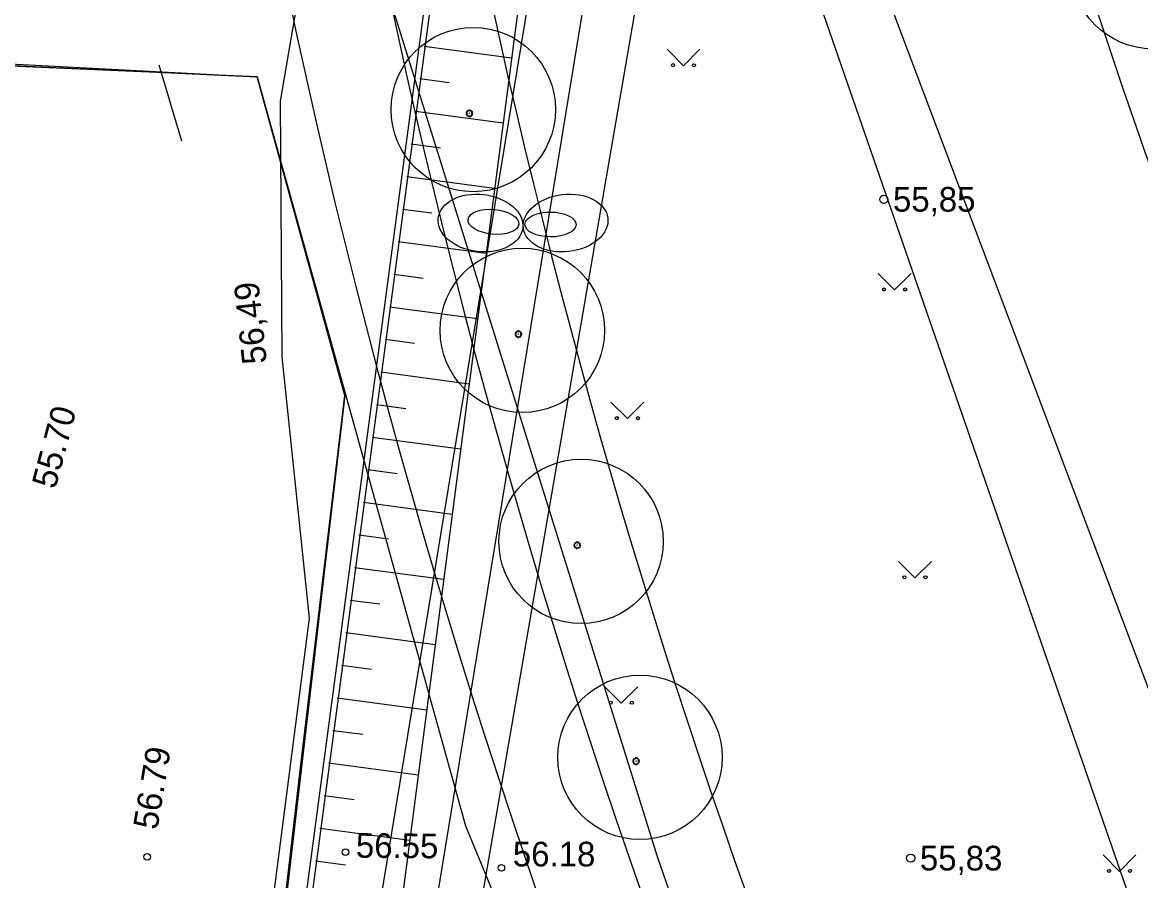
# Model space of a CAD drawing. Extents: x 9156 to 9809, y 2728 to 4000.
# Drawn here: x 9410.12 to 9444.15, y 3846.32 to 3872.43 of the extents above; entities that cross this region are included whole.
import ezdxf

# ---------------------------------------------------------------- set-up
doc = ezdxf.new("R2010")
doc.units = 0
for name, color, linetype in [('Level 12', 7, 'Continuous'), ('Level 14', 7, 'Continuous'), ('Level 16', 7, 'Continuous'), ('Level 17', 7, 'Continuous'), ('Level 18', 7, 'Continuous'), ('Level 41', 7, 'Continuous'), ('Level 54', 7, 'Continuous'), ('Level 56', 7, 'Continuous'), ('Level 6', 7, 'Continuous'), ('Level 7', 7, 'Continuous'), ('Level 8', 7, 'Continuous'), ('Level 9', 7, 'Continuous')]:
    doc.layers.add(name, color=color, linetype=linetype)

# ---------------------------------------------------------------- blocks, each defined once
blk = doc.blocks.new('MURU')
at = {"layer": 'Level 41'}
for p, q in [((-0.5, 0.5), (0, 0)), ((0, 0), (0.5, 0.5))]:
    blk.add_line(p, q, dxfattribs=at)
for centre in [(-0.32, 0.015), (0.32, 0.014)]:
    blk.add_circle(centre, 0.0466, dxfattribs=at)

msp = doc.modelspace()

# ---------------------------------------------------------------- linework, layer by layer
at = {"layer": 'Level 12'}
for p, q in [((9429.455, 3847.022), (9420.545, 3875.576)), ((9414.972, 3868.817), (9414.279, 3871.127)), ((9432.928, 3837.052), (9429.455, 3847.022))]:
    msp.add_line(p, q, dxfattribs=at)
at = {"layer": 'Level 14'}
msp.add_line((9444.967, 3842.49), (9431.28, 3881.958), dxfattribs=at)
at = {"layer": 'Level 16'}
msp.add_line((9449.679, 3838.123), (9432.161, 3884.564), dxfattribs=at)
at = {"layer": 'Level 17'}
for centre, radius, start, end in [((9631.829, 3934.713), 192.9, 187.13653, 212.29226), ((9631.829, 3934.713), 195.9, 187.89598, 211.0202), ((9639.344, 3919.894), 226, 185.96508, 207.05054), ((9639.344, 3919.894), 223, 186.63117, 207.05059)]:
    msp.add_arc(centre, radius, start, end, dxfattribs=at)
at = {"layer": 'Level 18'}
for centre, radius, start, end in [((9631.829, 3934.713), 198.9, 190.27283, 207.99609), ((9639.344, 3919.894), 220, 188.1609, 207.05049)]:
    msp.add_arc(centre, radius, start, end, dxfattribs=at)
at = {"layer": 'Level 54'}
for p, q in [((9428.052, 3915.601), (9415.976, 3825.147)), ((9427.378, 3909.376), (9416.171, 3825.133)), ((9419.432, 3836.064), (9425.772, 3874.586)), ((9429.001, 3874.205), (9422.209, 3834.878)), ((9422.347, 3871.71), (9425.006, 3871.355)), ((9422.215, 3870.719), (9423.102, 3870.601)), ((9422.082, 3869.728), (9424.747, 3869.372)), ((9421.95, 3868.737), (9422.839, 3868.618)), ((9421.818, 3867.746), (9424.489, 3867.389)), ((9421.685, 3866.754), (9422.577, 3866.635)), ((9421.553, 3865.763), (9424.23, 3865.406)), ((9421.42, 3864.772), (9422.314, 3864.653)), ((9421.288, 3863.781), (9423.972, 3863.422)), ((9421.156, 3862.79), (9422.051, 3862.67)), ((9421.023, 3861.798), (9423.713, 3861.439)), ((9420.891, 3860.807), (9421.789, 3860.687)), ((9420.758, 3859.816), (9423.455, 3859.456)), ((9420.626, 3858.825), (9421.526, 3858.705)), ((9420.494, 3857.834), (9423.196, 3857.473)), ((9420.361, 3856.842), (9421.263, 3856.722)), ((9420.229, 3855.851), (9422.938, 3855.489)), ((9420.097, 3854.86), (9421, 3854.739)), ((9419.964, 3853.869), (9422.679, 3853.506)), ((9419.832, 3852.878), (9420.738, 3852.757)), ((9419.699, 3851.886), (9422.421, 3851.523)), ((9419.567, 3850.895), (9420.475, 3850.774)), ((9419.435, 3849.904), (9422.162, 3849.54)), ((9419.302, 3848.913), (9420.212, 3848.791)), ((9419.17, 3847.922), (9421.904, 3847.556)), ((9419.037, 3846.93), (9419.95, 3846.809))]:
    msp.add_line(p, q, dxfattribs=at)
for points in [[(9415.997, 3832.136), (9418.853, 3854.304), (9418.853, 3854.304), (9418.027, 3862.261), (9417.976, 3870.031), (9426.142, 3917.687)], [(9419.311, 3824.906), (9430.024, 3890.161), (9433.2, 3889.656), (9434.423, 3896.884), (9431.507, 3897.561), (9431.927, 3902.125)], [(9428.218, 3901.358), (9428.633, 3899.185), (9420.75, 3838.705)]]:
    msp.add_lwpolyline(points, dxfattribs=at)
for centre, radius in [((9436.332, 3867.048), 0.125), ((9419.952, 3847.192), 0.1), ((9413.916, 3847.05), 0.1), ((9437.151, 3847.008), 0.125), ((9437.151, 3847.008), 0.125), ((9424.694, 3846.712), 0.1)]:
    msp.add_circle(centre, radius, dxfattribs=at)
at = {"layer": 'Level 56'}
for centre, radius, start, end in [((9631.829, 3934.713), 192.9, 187.13653, 212.29226), ((9631.829, 3934.713), 195.9, 187.89598, 211.0202), ((9631.829, 3934.713), 198.9, 190.27283, 207.99609), ((9639.344, 3919.894), 226, 185.96508, 207.05054), ((9639.344, 3919.894), 223, 186.63117, 207.05059), ((9639.344, 3919.894), 220, 188.1609, 207.05049)]:
    msp.add_arc(centre, radius, start, end, dxfattribs=at)
at = {"layer": 'Level 6'}
msp.add_line((9418.608, 3850.018), (9419.931, 3861.081), dxfattribs=at)
msp.add_lwpolyline([(9406.335, 3871.284), (9417.264, 3870.77), (9419.931, 3861.081), (9410.086, 3776.653), (9389.428, 3778.75), (9392.066, 3801.386), (9401.769, 3871.605)], close=True, dxfattribs=at)
for points in [[(9419.931, 3861.081), (9417.264, 3870.77), (9406.215, 3871.248), (9405.858, 3871.32)], [(9397.586, 3777.922), (9410.086, 3776.653), (9418.608, 3850.018)]]:
    msp.add_lwpolyline(points, dxfattribs=at)
at = {"layer": 'Level 7'}
for p, q in [((9397.252, 3871.834), (9417.264, 3870.77)), ((9417.264, 3870.77), (9423.602, 3847.995)), ((9423.602, 3847.995), (9436.729, 3816.345))]:
    msp.add_line(p, q, dxfattribs=at)
at = {"layer": 'Level 8'}
for centre, major_axis, ratio in [((9424.058, 3866.327), (1.285, -0.15), 0.674652), ((9424.058, 3866.327), (1.285, -0.15), 0.674652), ((9424.058, 3866.327), (1.285, -0.15), 0.674652), ((9424.058, 3866.327), (1.285, -0.15), 0.674652), ((9426.65, 3866.327), (-1.285, -0.15), 0.674652), ((9426.65, 3866.327), (-1.285, -0.15), 0.674652), ((9426.65, 3866.327), (-1.285, -0.15), 0.674652), ((9426.65, 3866.327), (-1.285, -0.15), 0.674652), ((9424.453, 3866.364), (0.774, -0.072), 0.486914), ((9424.453, 3866.364), (0.774, -0.072), 0.486914), ((9424.453, 3866.364), (0.774, -0.072), 0.486914), ((9424.453, 3866.364), (0.774, -0.072), 0.486914), ((9426.19, 3866.284), (-0.778, 0.002), 0.486914), ((9426.19, 3866.284), (-0.778, 0.002), 0.486914), ((9426.19, 3866.284), (-0.778, 0.002), 0.486914), ((9426.19, 3866.284), (-0.778, 0.002), 0.486914)]:
    msp.add_ellipse(centre, major_axis=major_axis, ratio=ratio, dxfattribs=at)
at = {"layer": 'Level 9'}
for p, q in [((9423.662, 3869.715), (9423.645, 3869.729)), ((9423.667, 3869.748), (9423.678, 3869.729)), ((9423.7, 3869.739), (9423.693, 3869.76)), ((9423.721, 3869.764), (9423.721, 3869.742)), ((9423.743, 3869.739), (9423.749, 3869.76)), ((9423.775, 3869.748), (9423.765, 3869.729)), ((9423.781, 3869.715), (9423.797, 3869.729)), ((9423.643, 3869.675), (9423.622, 3869.678)), ((9423.622, 3869.649), (9423.643, 3869.653)), ((9423.63, 3869.705), (9423.65, 3869.697)), ((9423.65, 3869.63), (9423.63, 3869.621)), ((9423.645, 3869.597), (9423.661, 3869.612)), ((9423.679, 3869.597), (9423.667, 3869.579)), ((9423.692, 3869.567), (9423.698, 3869.588)), ((9423.732, 3869.662), (9423.711, 3869.662)), ((9423.721, 3869.651), (9423.721, 3869.672)), ((9423.721, 3869.584), (9423.721, 3869.562)), ((9423.749, 3869.566), (9423.744, 3869.587)), ((9423.763, 3869.596), (9423.776, 3869.578)), ((9423.798, 3869.598), (9423.782, 3869.612)), ((9423.813, 3869.705), (9423.793, 3869.695)), ((9423.793, 3869.631), (9423.813, 3869.622)), ((9423.799, 3869.674), (9423.821, 3869.678)), ((9423.821, 3869.649), (9423.8, 3869.653)), ((9425.113, 3862.931), (9425.135, 3862.934)), ((9425.135, 3862.957), (9425.114, 3862.959)), ((9425.122, 3862.987), (9425.142, 3862.979)), ((9425.154, 3862.997), (9425.137, 3863.011)), ((9425.159, 3863.03), (9425.17, 3863.011)), ((9425.191, 3863.021), (9425.185, 3863.042)), ((9425.224, 3862.944), (9425.203, 3862.944)), ((9425.213, 3863.046), (9425.213, 3863.024)), ((9425.213, 3862.933), (9425.213, 3862.954)), ((9425.234, 3863.021), (9425.241, 3863.042)), ((9425.267, 3863.03), (9425.256, 3863.011)), ((9425.272, 3862.997), (9425.289, 3863.011)), ((9425.305, 3862.987), (9425.285, 3862.977)), ((9425.291, 3862.956), (9425.313, 3862.96)), ((9425.313, 3862.931), (9425.291, 3862.935)), ((9425.141, 3862.912), (9425.122, 3862.903)), ((9425.137, 3862.879), (9425.153, 3862.894)), ((9425.171, 3862.879), (9425.158, 3862.86)), ((9425.184, 3862.849), (9425.19, 3862.87)), ((9425.213, 3862.866), (9425.212, 3862.844)), ((9425.241, 3862.848), (9425.235, 3862.869)), ((9425.255, 3862.878), (9425.267, 3862.86)), ((9425.29, 3862.88), (9425.274, 3862.894)), ((9425.285, 3862.913), (9425.305, 3862.904)), ((9426.925, 3856.537), (9426.904, 3856.54)), ((9426.904, 3856.512), (9426.925, 3856.515)), ((9426.912, 3856.568), (9426.932, 3856.559)), ((9426.931, 3856.493), (9426.912, 3856.483)), ((9426.944, 3856.578), (9426.927, 3856.591)), ((9426.927, 3856.46), (9426.943, 3856.474)), ((9426.949, 3856.61), (9426.96, 3856.592)), ((9426.961, 3856.459), (9426.949, 3856.441)), ((9426.982, 3856.601), (9426.975, 3856.622)), ((9427.014, 3856.524), (9426.993, 3856.524)), ((9427.003, 3856.626), (9427.003, 3856.604)), ((9427.003, 3856.514), (9427.003, 3856.535)), ((9427.025, 3856.601), (9427.031, 3856.622)), ((9427.045, 3856.459), (9427.057, 3856.441)), ((9427.057, 3856.61), (9427.046, 3856.591)), ((9427.063, 3856.577), (9427.079, 3856.592)), ((9427.08, 3856.461), (9427.064, 3856.475)), ((9427.095, 3856.567), (9427.075, 3856.558)), ((9427.075, 3856.494), (9427.095, 3856.485)), ((9427.081, 3856.537), (9427.103, 3856.541)), ((9427.103, 3856.512), (9427.081, 3856.516)), ((9426.974, 3856.429), (9426.98, 3856.45)), ((9427.003, 3856.447), (9427.002, 3856.425)), ((9427.031, 3856.429), (9427.025, 3856.45)), ((9428.702, 3849.999), (9428.722, 3849.991)), ((9428.734, 3850.009), (9428.717, 3850.023)), ((9428.739, 3850.041), (9428.75, 3850.023)), ((9428.772, 3850.033), (9428.765, 3850.053)), ((9428.793, 3850.057), (9428.793, 3850.036)), ((9428.815, 3850.033), (9428.821, 3850.054)), ((9428.847, 3850.042), (9428.837, 3850.023)), ((9428.853, 3850.009), (9428.869, 3850.023)), ((9428.885, 3849.999), (9428.865, 3849.989)), ((9428.715, 3849.968), (9428.694, 3849.971)), ((9428.694, 3849.943), (9428.715, 3849.946)), ((9428.722, 3849.924), (9428.702, 3849.914)), ((9428.717, 3849.891), (9428.733, 3849.906)), ((9428.751, 3849.89), (9428.739, 3849.872)), ((9428.764, 3849.86), (9428.77, 3849.881)), ((9428.804, 3849.956), (9428.783, 3849.956)), ((9428.793, 3849.945), (9428.793, 3849.966)), ((9428.793, 3849.878), (9428.793, 3849.856)), ((9428.821, 3849.86), (9428.816, 3849.881)), ((9428.835, 3849.89), (9428.847, 3849.872)), ((9428.87, 3849.892), (9428.854, 3849.906)), ((9428.865, 3849.925), (9428.885, 3849.916)), ((9428.871, 3849.968), (9428.893, 3849.972)), ((9428.893, 3849.943), (9428.872, 3849.947))]:
    msp.add_line(p, q, dxfattribs=at)
for centre in [(9444.521, 3874.125), (9423.839, 3869.779), (9425.331, 3863.061), (9427.121, 3856.642), (9428.911, 3850.073)]:
    msp.add_circle(centre, 2.5, dxfattribs=at)
for centre, radius, start, end in [((9423.721, 3869.663), 0.101, 122.8434, 139.0222), ((9423.721, 3869.663), 0.0788, 105.9559, 123.0564), ((9423.721, 3869.663), 0.101, 90.0356, 106.342), ((9423.721, 3869.663), 0.0788, 74.31, 90.043), ((9423.721, 3869.663), 0.101, 57.6108, 74.1981), ((9423.721, 3869.663), 0.0788, 41.2062, 56.7795), ((9423.721, 3869.663), 0.101, 24.5394, 40.9852), ((9423.721, 3869.663), 0.101, 155.3123, 171.7042), ((9423.721, 3869.663), 0.101, 187.9671, 204.8625), ((9423.721, 3869.663), 0.0788, 171.5431, 187.6203), ((9423.721, 3869.663), 0.101, 220.7122, 237.1166), ((9423.721, 3869.663), 0.0788, 138.6432, 154.5795), ((9423.721, 3869.663), 0.0788, 204.4529, 220.4774), ((9423.721, 3869.663), 0.0788, 237.451, 253.0843), ((9423.721, 3869.663), 0.101, 253.2952, 269.5718), ((9423.721, 3869.663), 0.0788, 269.9461, 286.3473), ((9423.721, 3869.663), 0.101, 285.972, 302.5562), ((9423.721, 3869.663), 0.0788, 302.254, 320.086), ((9423.721, 3869.663), 0.0788, 8.0619, 24.0332), ((9423.721, 3869.663), 0.0788, 336.0557, 352.7558), ((9423.721, 3869.663), 0.101, 319.7777, 336.0738), ((9423.721, 3869.663), 0.101, 352.27, 8.583), ((9425.213, 3862.945), 0.101, 155.3123, 171.7042), ((9425.213, 3862.945), 0.101, 187.9671, 204.8625), ((9425.213, 3862.945), 0.0788, 171.5431, 187.6203), ((9425.213, 3862.945), 0.101, 122.8434, 139.0222), ((9425.213, 3862.945), 0.0788, 138.6432, 154.5795), ((9425.213, 3862.945), 0.0788, 105.9559, 123.0564), ((9425.213, 3862.945), 0.101, 90.0356, 106.342), ((9425.213, 3862.945), 0.0788, 74.31, 90.043), ((9425.213, 3862.945), 0.101, 57.6108, 74.1981), ((9425.213, 3862.945), 0.0788, 41.2062, 56.7795), ((9425.213, 3862.945), 0.0788, 8.0619, 24.0332), ((9425.213, 3862.945), 0.0788, 336.0557, 352.7558), ((9425.213, 3862.945), 0.101, 24.5394, 40.9852), ((9425.213, 3862.945), 0.101, 352.27, 8.583), ((9425.213, 3862.945), 0.101, 220.7122, 237.1166), ((9425.213, 3862.945), 0.0788, 204.4529, 220.4774), ((9425.213, 3862.945), 0.0788, 237.451, 253.0843), ((9425.213, 3862.945), 0.101, 253.2952, 269.5718), ((9425.213, 3862.945), 0.0788, 269.9461, 286.3473), ((9425.213, 3862.945), 0.101, 285.972, 302.5562), ((9425.213, 3862.945), 0.0788, 302.254, 320.086), ((9425.213, 3862.945), 0.101, 319.7777, 336.0738), ((9427.003, 3856.525), 0.101, 155.3123, 171.7042), ((9427.003, 3856.525), 0.101, 187.9671, 204.8625), ((9427.003, 3856.525), 0.0788, 171.5431, 187.6203), ((9427.003, 3856.525), 0.101, 122.8434, 139.0222), ((9427.003, 3856.525), 0.101, 220.7122, 237.1166), ((9427.003, 3856.525), 0.0788, 204.4529, 220.4774), ((9427.003, 3856.525), 0.0788, 138.6432, 154.5795), ((9427.003, 3856.525), 0.0788, 105.9559, 123.0564), ((9427.003, 3856.525), 0.0788, 237.451, 253.0843), ((9427.003, 3856.525), 0.101, 90.0356, 106.342), ((9427.003, 3856.525), 0.0788, 74.31, 90.043), ((9427.003, 3856.525), 0.101, 57.6108, 74.1981), ((9427.003, 3856.525), 0.0788, 302.254, 320.086), ((9427.003, 3856.525), 0.0788, 41.2062, 56.7795), ((9427.003, 3856.525), 0.0788, 8.0619, 24.0332), ((9427.003, 3856.525), 0.0788, 336.0557, 352.7558), ((9427.003, 3856.525), 0.101, 24.5394, 40.9852), ((9427.003, 3856.525), 0.101, 319.7777, 336.0738), ((9427.003, 3856.525), 0.101, 352.27, 8.583), ((9427.003, 3856.525), 0.101, 253.2952, 269.5718), ((9427.003, 3856.525), 0.0788, 269.9461, 286.3473), ((9427.003, 3856.525), 0.101, 285.972, 302.5562), ((9428.793, 3849.957), 0.101, 155.3123, 171.7042), ((9428.793, 3849.957), 0.101, 122.8434, 139.0222), ((9428.793, 3849.957), 0.0788, 138.6432, 154.5795), ((9428.793, 3849.957), 0.0788, 105.9559, 123.0564), ((9428.793, 3849.957), 0.101, 90.0356, 106.342), ((9428.793, 3849.957), 0.0788, 74.31, 90.043), ((9428.793, 3849.957), 0.101, 57.6108, 74.1981), ((9428.793, 3849.957), 0.0788, 41.2062, 56.7795), ((9428.793, 3849.957), 0.101, 24.5394, 40.9852), ((9428.793, 3849.957), 0.101, 187.9671, 204.8625), ((9428.793, 3849.957), 0.0788, 171.5431, 187.6203), ((9428.793, 3849.957), 0.101, 220.7122, 237.1166), ((9428.793, 3849.957), 0.0788, 204.4529, 220.4774), ((9428.793, 3849.957), 0.0788, 237.451, 253.0843), ((9428.793, 3849.957), 0.101, 253.2952, 269.5718), ((9428.793, 3849.957), 0.0788, 269.9461, 286.3473), ((9428.793, 3849.957), 0.101, 285.972, 302.5562), ((9428.793, 3849.957), 0.0788, 302.254, 320.086), ((9428.793, 3849.957), 0.0788, 8.0619, 24.0332), ((9428.793, 3849.957), 0.0788, 336.0557, 352.7558), ((9428.793, 3849.957), 0.101, 319.7777, 336.0738), ((9428.793, 3849.957), 0.101, 352.27, 8.583)]:
    msp.add_arc(centre, radius, start, end, dxfattribs=at)

# ---------------------------------------------------------------- block references
at = {"layer": 'Level 54'}
for p in [(9430.235, 3871.114), (9436.661, 3864.291), (9428.528, 3860.377), (9437.28, 3855.536), (9428.344, 3851.723), (9443.505, 3846.605)]:
    msp.add_blockref('MURU', p, dxfattribs=at)

# ---------------------------------------------------------------- texts
for s, p in [(' 55,85', (9436.332, 3866.673)), ('56.18', (9425.044, 3846.755)), (' 55,83', (9437.151, 3846.633)), (' 55,83', (9437.151, 3846.633))]:
    msp.add_text(s, height=0.75, dxfattribs=at).set_placement(p)
for s, rotation, p in [(' 56,49', 95.937, (9417.589, 3861.796)), ('55.70', 75.0601, (9411.121, 3858.21)), ('56.79', 80.4355, (9414.223, 3847.849)), ('56.55', 359.5763, (9420.265, 3847.02))]:
    msp.add_text(s, height=0.75, rotation=rotation, dxfattribs=at).set_placement(p)

doc.saveas('drawing.dxf')
